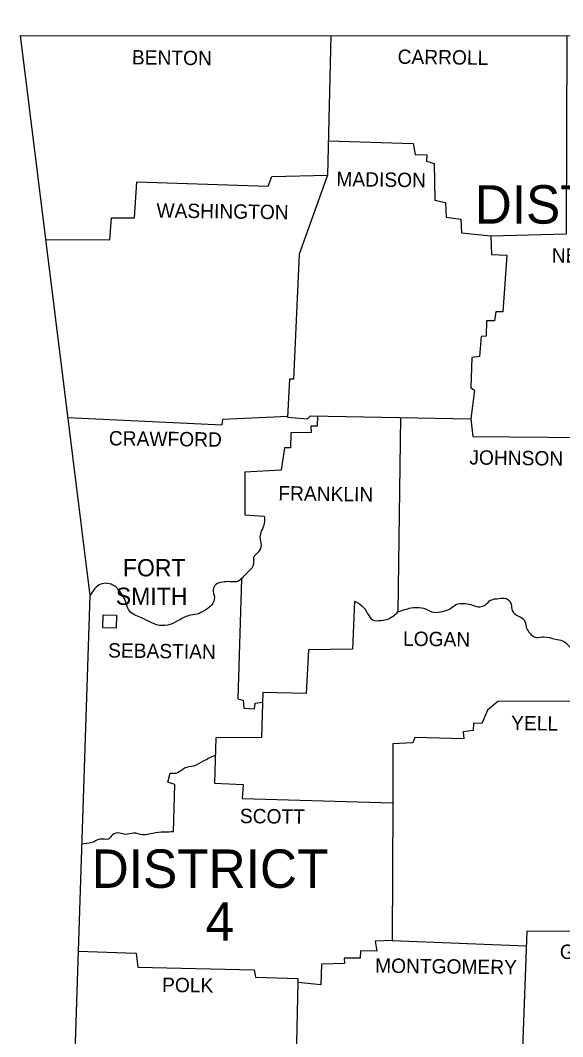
# Model space of a CAD drawing. Extents: x -819161 to 80911, y -6604 to 768454.
# Drawn here: x 60665 to 61547, y 7879 to 9531 of the extents above; entities that cross this region are included whole.
import ezdxf

# ---------------------------------------------------------------- set-up
doc = ezdxf.new("R2010")
doc.units = 0
doc.layers.add('Default', color=7, linetype='Continuous')

msp = doc.modelspace()

# ---------------------------------------------------------------- linework, layer by layer
at = {"layer": 'Default'}
msp.add_line((60768.8, 8192.1), (60764.8, 8191.6), dxfattribs=at)
for points in [[(60664.8, 9505.7), (61549.9, 9505.1), (62327.3, 9506.6), (63243.8, 9520.6), (63669, 9530.6)], [(60664.8, 9505.7), (60778.1, 8595.4), (60729, 7109.7)], [(61170, 9505.3), (61164.2, 9278.9)], [(61165.6, 9334.6), (61303.8, 9330.2), (61306.9, 9312.7), (61325.9, 9312.1), (61325.2, 9301.5), (61338, 9298.1), (61339.2, 9238), (61356.4, 9234.3), (61357.6, 9210.6), (61381.3, 9207.5), (61382.5, 9185.4), (61429.8, 9180.3), (61553, 9183.6), (61554, 9505.1)], [(60706.1, 9174.2), (60810.5, 9173.9), (60813, 9209.7), (60850.6, 9209.7), (60854.1, 9268.2), (61067.9, 9260.8), (61074.1, 9276.9), (61164.2, 9278.9), (61118.3, 9150.6), (61109.3, 8947.4), (61102.7, 8947.1), (61099.6, 8885.7), (61131.7, 8882.9), (61136.6, 8887.9), (61397.7, 8882.9), (61400.5, 8854)], [(61429.8, 9180.3), (61431, 9150), (61456.3, 9148.7), (61449.7, 9056.6), (61438.2, 9056.9), (61436, 9042.3), (61423, 9042), (61422.3, 9017.1), (61414.2, 9016.5), (61411.4, 8984.1), (61399.3, 8982.5), (61397.7, 8933.4), (61403.3, 8929.3), (61397.7, 8882.9)], [(61400.5, 8854), (62008.3, 8848.7), (62011.5, 8906.6), (62154.1, 8904.7)], [(60742.1, 8885.2), (60993.2, 8873.3), (60994.4, 8882.3), (61099.7, 8887)], [(61148.1, 8887.7), (61147.5, 8870.8), (61137.3, 8870.8), (61137.6, 8860.8), (61104.6, 8860.2), (61104, 8835.9), (61094.6, 8835.9), (61089.3, 8799.2), (61030.2, 8796.1), (61029.9, 8727), (61061.6, 8724.5)], [(61282.9, 8885.1), (61278.9, 8568.9)], [(61024.5, 8622.8), (61018.7, 8427.6), (61027.4, 8425.5), (61028.6, 8412.4), (61045.5, 8411.5), (61046.7, 8420.5), (61058.7, 8422.5)], [(61208.5, 8586.4), (61204.8, 8508.2), (61133.5, 8507.6), (61129.5, 8436.4), (61059.1, 8438.2), (61057, 8365.1), (60982.9, 8364.2), (60980.4, 8290.7), (61027.4, 8288.2), (61025.5, 8265.5), (61270.5, 8258.8)], [(61568.3, 8502.6), (61565.8, 8423.9), (61441.3, 8423.3), (61424.8, 8409.3), (61415.2, 8387.5), (61401.8, 8388.1), (61401.2, 8376), (61385.3, 8374.1), (61385.9, 8362.9), (61306.6, 8364.8), (61303.4, 8356.1), (61270.8, 8354.8), (61270.5, 8258.8)], [(60914.1, 8211.3), (60916, 8288.5), (60904.8, 8292.3), (60908.5, 8306.9)], [(61270.5, 8258.8), (61269.8, 8034.6), (61242.1, 8034), (61244.6, 8017.8), (61218.2, 8018.1), (61217.6, 8005.9), (61191.7, 8005.9), (61192.3, 7997.5), (61154.4, 7996.3), (61153.4, 7963), (61116.4, 7966.4), (61110.2, 7696.9)], [(61891.6, 8113.9), (61713, 8119.2), (61708, 8048.9), (61488.6, 8050.1), (61475.1, 7682.7)], [(61269.8, 8034.6), (61487.7, 8026.1)], [(60759, 8017.5), (60853.4, 8014.4), (60855.9, 7991.3), (61045.1, 7987.3), (61047.3, 7975.4), (61116.4, 7973.3), (61116.4, 7966.4)]]:
    msp.add_lwpolyline(points, dxfattribs=at)
msp.add_lwpolyline([(60799, 8543.1), (60799.6, 8564.3), (60821.4, 8563.6), (60820.8, 8542.5)], close=True, dxfattribs=at)
for points in [[(61061.6, 8724.5), (61061.6, 8713), (61057.3, 8701.2), (61054.5, 8690.6), (61056.3, 8676.9), (61051.4, 8666), (61044.2, 8657), (61044.2, 8646.4), (61036.1, 8634.9), (61027.1, 8625.9), (61019.6, 8619), (61005.6, 8618.1), (60994.1, 8617.5), (60982.9, 8613.4), (60978.5, 8605), (60980.4, 8592.6), (60976.1, 8580.4), (60964.9, 8571.4), (60952.1, 8565.2), (60939, 8563), (60920.7, 8554.3), (60904.5, 8547.5), (60886.7, 8548.1), (60870.6, 8555.2), (60855.6, 8561.8), (60844.1, 8568.6), (60835.1, 8588.5), (60828.9, 8599.7), (60818.3, 8610.9), (60806.1, 8615.3), (60795.6, 8614.1), (60778.1, 8595.4)], [(61278.9, 8568.9), (61297.2, 8574.8), (61310.3, 8576.4), (61323.7, 8573.9), (61337.4, 8568.3), (61351.7, 8569.9), (61362.6, 8573.6), (61373.8, 8580.8), (61385.6, 8582.9), (61397.4, 8580.8), (61409.6, 8577.3), (61422.3, 8581.4), (61430.1, 8588.2), (61443.2, 8590.7), (61455, 8590.7), (61463.1, 8581.4), (61464.7, 8571.1), (61475.2, 8562.1), (61484.3, 8555.9), (61487.4, 8544.7), (61492, 8536.3), (61497, 8530.7), (61504.2, 8527.5), (61516.3, 8528.5), (61535, 8524.7), (61546.8, 8522.2), (61558, 8512.6), (61568.3, 8502.6)], [(61208.5, 8586.4), (61220.4, 8578.9), (61229.7, 8566.4), (61237.8, 8555.9), (61251.8, 8555.2), (61262.7, 8557.4), (61278.9, 8568.9)], [(60908.5, 8306.9), (60920.3, 8307.8), (60931.9, 8315.3), (60947.1, 8319), (60962.7, 8326.8), (60981.9, 8336)], [(60914.1, 8211.3), (60898.6, 8211), (60880.2, 8208.9), (60863.7, 8206.7), (60849.1, 8209.5), (60835.7, 8207.3), (60826.4, 8209.5), (60814.8, 8206.7), (60808, 8199.8), (60794.3, 8199.8), (60784.7, 8195.5), (60768.8, 8192.1)]]:
    msp.add_spline(points, degree=3, dxfattribs=at)

# ---------------------------------------------------------------- texts
for s, rotation, p in [('CARROLL', 359.267, (61278.3, 9459.9)), ('BENTON', 359.2874, (60846.2, 9459)), ('MADISON', 359.217, (61178.7, 9261.1)), ('WASHINGTON', 359.2079, (60886.1, 9210)), ('NEWTON', 359.303, (61529, 9136.9)), ('CRAWFORD', 359.2748, (60808.7, 8839.7)), ('JOHNSON', 359.2575, (61395, 8808.6)), ('FRANKLIN', 359.1782, (61084.3, 8750.4)), ('LOGAN', 359.3076, (61287.1, 8513.9)), ('SEBASTIAN', 359.1959, (60807.5, 8494.9)), ('YELL', 359.3097, (61463, 8376.9)), ('SCOTT', 359.32, (61021.8, 8225.7)), ('GARLAND', 359.2717, (61542.1, 8005)), ('MONTGOMERY', 359.2707, (61241.7, 7982.6)), ('POLK', 359.3233, (60895.3, 7951.2))]:
    msp.add_text(s, height=23.34, rotation=rotation, dxfattribs=at).set_placement(p)
for s, height, p in [('DISTRICT 9', 62.43, (61403.8, 9200.1)), ('FORT', 28.01, (60831.7, 8626.8)), ('SMITH', 28.01, (60820.1, 8580.4)), ('DISTRICT', 62.43, (60780.9, 8120.4)), ('4', 62.4, (60966, 8034.6))]:
    msp.add_text(s, height=height, dxfattribs=at).set_placement(p)

doc.saveas('drawing.dxf')
